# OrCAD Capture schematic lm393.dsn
size A
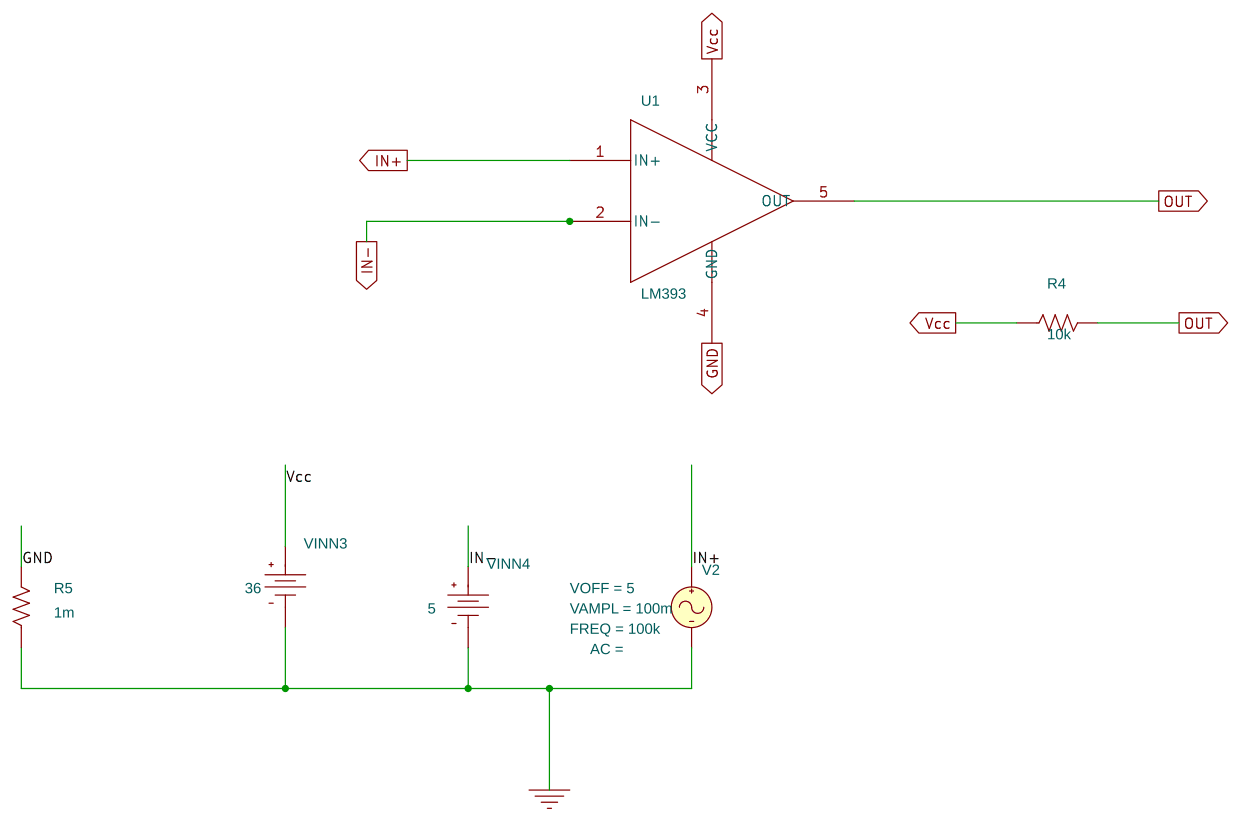
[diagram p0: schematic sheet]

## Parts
R4  10k  [AXRC05]
R5  1m  [AXRC05]
U1  LM393
V2  VSIN
VINN3  VDC
VINN4  VDC

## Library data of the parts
R4 R5 = R
U1 = LM393
V2 = VSIN: FREQ: 100k; VAMPL: 100m; VOFF: 5
VINN3 = VDC: DC: 36
VINN4 = VDC: DC: 5

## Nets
GND: R5.2 U1.4(GND)
Vcc: R4.1 U1.3(VCC) VINN3.0(+)
0: R5.1 V2.2(-) VINN3.1(-) VINN4.1(-)
IN+: U1.1(IN+) V2.1(+)
IN-: U1.2(IN-) VINN4.0(+)
OUT: R4.2 U1.5(OUT)
